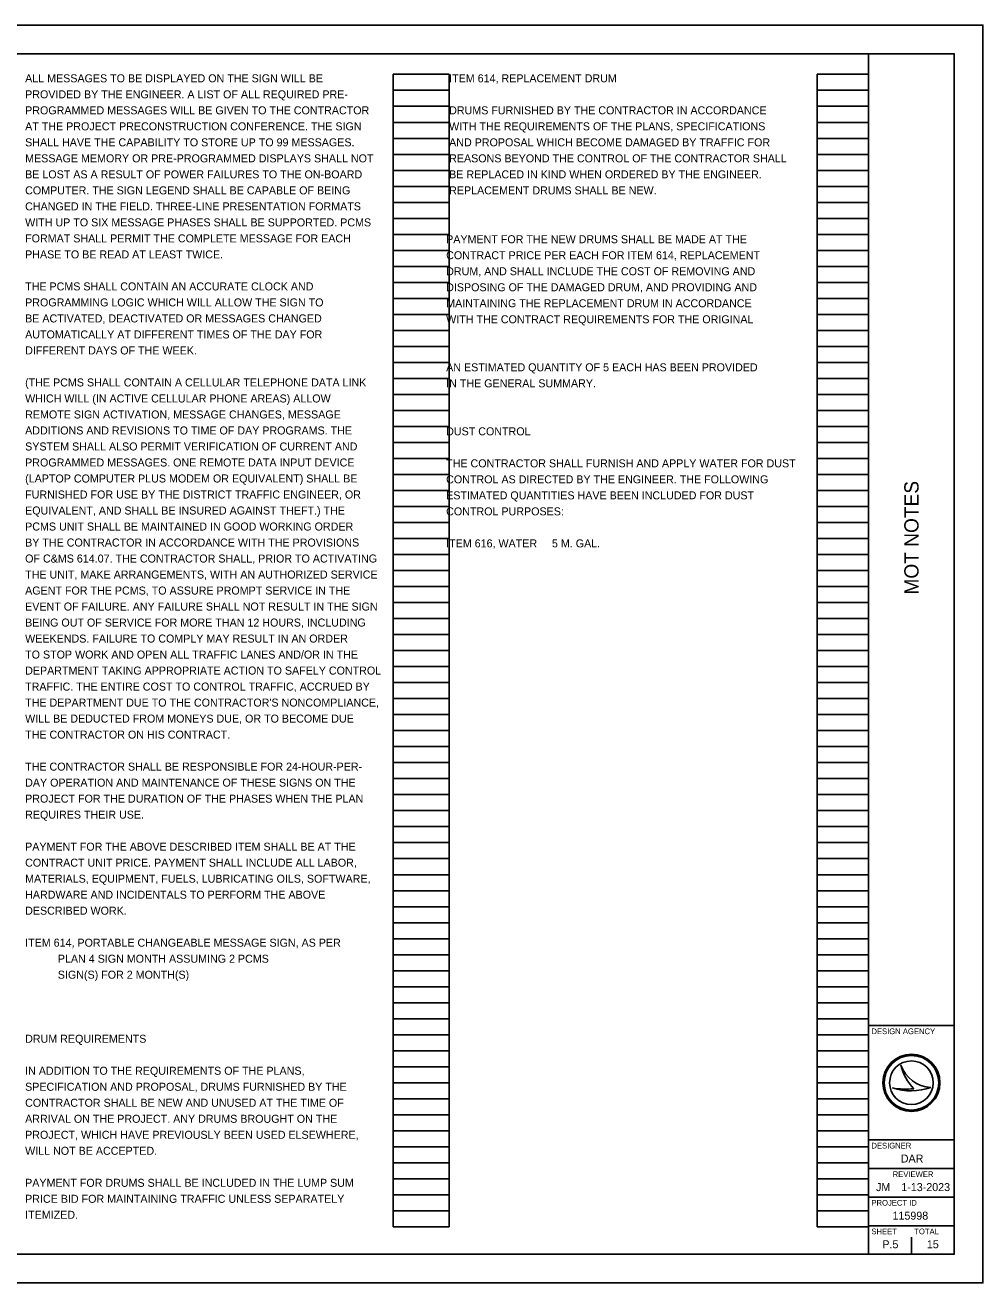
# Model space of a CAD drawing. Extents: x 0 to 34, y 0 to 22.
# Drawn here: x 17.24 to 34, y 0 to 22 of the extents above; entities that cross this region are included whole.
import ezdxf

# ---------------------------------------------------------------- set-up
doc = ezdxf.new("R2010")
doc.units = 0
for name, color, linetype in [('SH_Border', 7, 'Continuous'), ('SH_Cut_Line', 7, 'Continuous'), ('SH_Data', 7, 'Continuous'), ('SH_Text', 7, 'Continuous')]:
    doc.layers.add(name, color=color, linetype=linetype)

msp = doc.modelspace()

# ---------------------------------------------------------------- linework, layer by layer
at = {"layer": 'SH_Border'}
for p, q in [((32, 0.5), (32, 21.5)), ((32, 4.5), (33.5, 4.5)), ((32, 2.5), (33.5, 2.5)), ((32, 2), (33.5, 2)), ((32, 1.5), (33.5, 1.5)), ((32, 1), (33.5, 1))]:
    msp.add_line(p, q, dxfattribs=at)
msp.add_lwpolyline([(1.5, 21.5), (33.5, 21.5), (33.5, 0.5), (1.5, 0.5)], close=True, dxfattribs=at)
at = {"layer": 'SH_Cut_Line'}
msp.add_lwpolyline([(0, 0), (34, 0), (34, 22), (0, 22)], close=True, dxfattribs=at)
at = {"layer": 'SH_Data'}
for p, q in [((23.68, 0.98), (23.68, 21.14)), ((23.68, 21.14), (24.66, 21.14)), ((24.66, 0.98), (24.66, 21.14)), ((31.1, 0.98), (31.1, 21.14)), ((31.1, 21.14), (32, 21.14)), ((32, 0.98), (32, 21.14)), ((23.68, 20.86), (24.66, 20.86)), ((31.1, 20.86), (32, 20.86)), ((23.68, 20.58), (24.66, 20.58)), ((31.1, 20.58), (32, 20.58)), ((23.68, 20.3), (24.66, 20.3)), ((31.1, 20.3), (32, 20.3)), ((23.68, 20.02), (24.66, 20.02)), ((31.1, 20.02), (32, 20.02)), ((23.68, 19.74), (24.66, 19.74)), ((31.1, 19.74), (32, 19.74)), ((23.68, 19.46), (24.66, 19.46)), ((31.1, 19.46), (32, 19.46)), ((23.68, 19.18), (24.66, 19.18)), ((31.1, 19.18), (32, 19.18)), ((23.68, 18.9), (24.66, 18.9)), ((31.1, 18.9), (32, 18.9)), ((23.68, 18.62), (24.66, 18.62)), ((31.1, 18.62), (32, 18.62)), ((23.68, 18.34), (24.66, 18.34)), ((31.1, 18.34), (32, 18.34)), ((23.68, 18.06), (24.66, 18.06)), ((31.1, 18.06), (32, 18.06)), ((23.68, 17.78), (24.66, 17.78)), ((31.1, 17.78), (32, 17.78)), ((23.68, 17.5), (24.66, 17.5)), ((31.1, 17.5), (32, 17.5)), ((23.68, 17.22), (24.66, 17.22)), ((31.1, 17.22), (32, 17.22)), ((23.68, 16.94), (24.66, 16.94)), ((31.1, 16.94), (32, 16.94)), ((23.68, 16.66), (24.66, 16.66)), ((31.1, 16.66), (32, 16.66)), ((23.68, 16.38), (24.66, 16.38)), ((31.1, 16.38), (32, 16.38)), ((23.68, 16.1), (24.66, 16.1)), ((31.1, 16.1), (32, 16.1)), ((23.68, 15.82), (24.66, 15.82)), ((31.1, 15.82), (32, 15.82)), ((23.68, 15.54), (24.66, 15.54)), ((31.1, 15.54), (32, 15.54)), ((23.68, 15.26), (24.66, 15.26)), ((31.1, 15.26), (32, 15.26)), ((23.68, 14.98), (24.66, 14.98)), ((31.1, 14.98), (32, 14.98)), ((23.68, 14.7), (24.66, 14.7)), ((31.1, 14.7), (32, 14.7)), ((23.68, 14.42), (24.66, 14.42)), ((31.1, 14.42), (32, 14.42)), ((23.68, 14.14), (24.66, 14.14)), ((31.1, 14.14), (32, 14.14)), ((23.68, 13.86), (24.66, 13.86)), ((31.1, 13.86), (32, 13.86)), ((23.68, 13.58), (24.66, 13.58)), ((31.1, 13.58), (32, 13.58)), ((23.68, 13.3), (24.66, 13.3)), ((31.1, 13.3), (32, 13.3)), ((23.68, 13.02), (24.66, 13.02)), ((31.1, 13.02), (32, 13.02)), ((23.68, 12.74), (24.66, 12.74)), ((31.1, 12.74), (32, 12.74)), ((23.68, 12.46), (24.66, 12.46)), ((31.1, 12.46), (32, 12.46)), ((23.68, 12.18), (24.66, 12.18)), ((31.1, 12.18), (32, 12.18)), ((23.68, 11.9), (24.66, 11.9)), ((31.1, 11.9), (32, 11.9)), ((23.68, 11.62), (24.66, 11.62)), ((31.1, 11.62), (32, 11.62)), ((23.68, 11.34), (24.66, 11.34)), ((31.1, 11.34), (32, 11.34)), ((23.68, 11.06), (24.66, 11.06)), ((31.1, 11.06), (32, 11.06)), ((23.68, 10.78), (24.66, 10.78)), ((31.1, 10.78), (32, 10.78)), ((23.68, 10.5), (24.66, 10.5)), ((31.1, 10.5), (32, 10.5)), ((23.68, 10.22), (24.66, 10.22)), ((31.1, 10.22), (32, 10.22)), ((23.68, 9.94), (24.66, 9.94)), ((31.1, 9.94), (32, 9.94)), ((23.68, 9.66), (24.66, 9.66)), ((31.1, 9.66), (32, 9.66)), ((23.68, 9.38), (24.66, 9.38)), ((31.1, 9.38), (32, 9.38)), ((23.68, 9.1), (24.66, 9.1)), ((31.1, 9.1), (32, 9.1)), ((23.68, 8.82), (24.66, 8.82)), ((31.1, 8.82), (32, 8.82)), ((23.68, 8.54), (24.66, 8.54)), ((31.1, 8.54), (32, 8.54)), ((23.68, 8.26), (24.66, 8.26)), ((31.1, 8.26), (32, 8.26)), ((23.68, 7.98), (24.66, 7.98)), ((31.1, 7.98), (32, 7.98)), ((23.68, 7.7), (24.66, 7.7)), ((31.1, 7.7), (32, 7.7)), ((23.68, 7.42), (24.66, 7.42)), ((31.1, 7.42), (32, 7.42)), ((23.68, 7.14), (24.66, 7.14)), ((31.1, 7.14), (32, 7.14)), ((23.68, 6.86), (24.66, 6.86)), ((31.1, 6.86), (32, 6.86)), ((23.68, 6.58), (24.66, 6.58)), ((31.1, 6.58), (32, 6.58)), ((23.68, 6.3), (24.66, 6.3)), ((31.1, 6.3), (32, 6.3)), ((23.68, 6.02), (24.66, 6.02)), ((31.1, 6.02), (32, 6.02)), ((23.68, 5.74), (24.66, 5.74)), ((31.1, 5.74), (32, 5.74)), ((23.68, 5.46), (24.66, 5.46)), ((31.1, 5.46), (32, 5.46)), ((23.68, 5.18), (24.66, 5.18)), ((31.1, 5.18), (32, 5.18)), ((23.68, 4.9), (24.66, 4.9)), ((31.1, 4.9), (32, 4.9)), ((23.68, 4.62), (24.66, 4.62)), ((31.1, 4.62), (32, 4.62)), ((23.68, 4.34), (24.66, 4.34)), ((31.1, 4.34), (32, 4.34)), ((23.68, 4.06), (24.66, 4.06)), ((31.1, 4.06), (32, 4.06)), ((23.68, 3.78), (24.66, 3.78)), ((31.1, 3.78), (32, 3.78)), ((32.567, 3.81), (32.567, 3.81)), ((23.68, 3.5), (24.66, 3.5)), ((31.1, 3.5), (32, 3.5)), ((32.417, 3.41), (32.417, 3.41)), ((32.75, 3.5), (32.75, 3.5)), ((33.087, 3.419), (33.087, 3.419)), ((23.68, 3.22), (24.66, 3.22)), ((31.1, 3.22), (32, 3.22)), ((23.68, 2.94), (24.66, 2.94)), ((31.1, 2.94), (32, 2.94)), ((23.68, 2.66), (24.66, 2.66)), ((31.1, 2.66), (32, 2.66)), ((23.68, 2.38), (24.66, 2.38)), ((31.1, 2.38), (32, 2.38)), ((23.68, 2.1), (24.66, 2.1)), ((31.1, 2.1), (32, 2.1)), ((23.68, 1.82), (24.66, 1.82)), ((31.1, 1.82), (32, 1.82)), ((23.68, 1.54), (24.66, 1.54)), ((31.1, 1.54), (32, 1.54)), ((23.68, 1.26), (24.66, 1.26)), ((31.1, 1.26), (32, 1.26)), ((23.68, 0.98), (24.66, 0.98)), ((31.1, 0.98), (32, 0.98)), ((32.375, 0.675), (32.375, 0.675)), ((32.75, 0.5), (32.75, 0.8))]:
    msp.add_line(p, q, dxfattribs=at)
for radius in [0.5, 0.477, 0.477, 0.382]:
    msp.add_circle((32.75, 3.5), radius, dxfattribs=at)
for centre, radius, start, end in [((33.116, 3.998), 0.58, 198.9257, 198.9319), ((33.347, 3.97), 0.796, 191.6379, 191.6421), ((33.116, 3.998), 0.58, 198.9319, 267.1657), ((33.347, 3.97), 0.796, 191.6421, 226.0947), ((32.739, 4.37), 1.013, 251.4576, 290.0832), ((32.648, 4.654), 1.266, 259.4964, 259.4995), ((32.739, 4.37), 1.013, 251.4527, 251.4576), ((32.648, 4.654), 1.266, 259.4995, 276.6672)]:
    msp.add_arc(centre, radius, start, end, dxfattribs=at)

# ---------------------------------------------------------------- texts
msp.add_text('MOT NOTES', height=0.25, rotation=90, dxfattribs=at).set_placement((32.875, 12.04))
for s, height, p in [('DESIGN AGENCY', 0.1, (32.05, 4.35)), ('DESIGNER', 0.1, (32.05, 2.35)), ('DAR', 0.14, (32.564, 2.105)), ('REVIEWER', 0.1, (32.422, 1.85)), ('JM', 0.14, (32.13, 1.605)), ('1-13-2023', 0.14, (32.573, 1.605)), ('PROJECT ID', 0.1, (32.05, 1.35)), ('115998', 0.14, (32.419, 1.105)), ('SHEET', 0.1, (32.05, 0.85)), ('TOTAL', 0.1, (32.8, 0.85)), ('P.5', 0.14, (32.241, 0.605)), ('15', 0.14, (33.02, 0.605))]:
    msp.add_text(s, height=height, dxfattribs=at).set_placement(p)
at = {"layer": 'SH_Text'}
for s, p in [('ALL MESSAGES TO BE DISPLAYED ON THE SIGN WILL BE', (17.24, 21)), ('ITEM 614, REPLACEMENT DRUM', (24.66, 21)), ('PROVIDED BY THE ENGINEER. A LIST OF ALL REQUIRED PRE-', (17.24, 20.72)), ('PROGRAMMED MESSAGES WILL BE GIVEN TO THE CONTRACTOR', (17.24, 20.44)), ('DRUMS FURNISHED BY THE CONTRACTOR IN ACCORDANCE', (24.66, 20.44)), ('AT THE PROJECT PRECONSTRUCTION CONFERENCE. THE SIGN', (17.24, 20.16)), ('WITH THE REQUIREMENTS OF THE PLANS, SPECIFICATIONS', (24.66, 20.16)), ('SHALL HAVE THE CAPABILITY TO STORE UP TO 99 MESSAGES.', (17.24, 19.88)), ('AND PROPOSAL WHICH BECOME DAMAGED BY TRAFFIC FOR', (24.66, 19.88)), ('MESSAGE MEMORY OR PRE-PROGRAMMED DISPLAYS SHALL NOT', (17.24, 19.6)), ('REASONS BEYOND THE CONTROL OF THE CONTRACTOR SHALL', (24.66, 19.6)), ('BE LOST AS A RESULT OF POWER FAILURES TO THE ON-BOARD', (17.24, 19.32)), ('BE REPLACED IN KIND WHEN ORDERED BY THE ENGINEER.', (24.66, 19.32)), ('COMPUTER. THE SIGN LEGEND SHALL BE CAPABLE OF BEING', (17.24, 19.04)), ('REPLACEMENT DRUMS SHALL BE NEW.', (24.66, 19.04)), ('CHANGED IN THE FIELD. THREE-LINE PRESENTATION FORMATS', (17.24, 18.76)), ('WITH UP TO SIX MESSAGE PHASES SHALL BE SUPPORTED. PCMS', (17.24, 18.48)), ('FORMAT SHALL PERMIT THE COMPLETE MESSAGE FOR EACH', (17.24, 18.2)), ('PAYMENT FOR THE NEW DRUMS SHALL BE MADE AT THE', (24.608, 18.185)), ('PHASE TO BE READ AT LEAST TWICE.', (17.24, 17.92)), ('CONTRACT PRICE PER EACH FOR ITEM 614, REPLACEMENT', (24.608, 17.905)), ('DRUM, AND SHALL INCLUDE THE COST OF REMOVING AND', (24.608, 17.625)), ('THE PCMS SHALL CONTAIN AN ACCURATE CLOCK AND', (17.24, 17.36)), ('DISPOSING OF THE DAMAGED DRUM, AND PROVIDING AND', (24.608, 17.345)), ('PROGRAMMING LOGIC WHICH WILL ALLOW THE SIGN TO', (17.24, 17.08)), ('MAINTAINING THE REPLACEMENT DRUM IN ACCORDANCE', (24.608, 17.065)), ('BE ACTIVATED, DEACTIVATED OR MESSAGES CHANGED', (17.24, 16.8)), ('WITH THE CONTRACT REQUIREMENTS FOR THE ORIGINAL', (24.608, 16.785)), ('AUTOMATICALLY AT DIFFERENT TIMES OF THE DAY FOR', (17.24, 16.52)), ('DIFFERENT DAYS OF THE WEEK.', (17.24, 16.24)), ('AN ESTIMATED QUANTITY OF 5 EACH HAS BEEN PROVIDED', (24.608, 15.945)), ('(THE PCMS SHALL CONTAIN A CELLULAR TELEPHONE DATA LINK', (17.24, 15.68)), ('IN THE GENERAL SUMMARY.', (24.608, 15.665)), ('WHICH WILL (IN ACTIVE CELLULAR PHONE AREAS) ALLOW', (17.24, 15.4)), ('REMOTE SIGN ACTIVATION, MESSAGE CHANGES, MESSAGE', (17.24, 15.12)), ('ADDITIONS AND REVISIONS TO TIME OF DAY PROGRAMS. THE', (17.24, 14.84)), ('DUST CONTROL', (24.608, 14.825)), ('SYSTEM SHALL ALSO PERMIT VERIFICATION OF CURRENT AND', (17.24, 14.56)), ('PROGRAMMED MESSAGES. ONE REMOTE DATA INPUT DEVICE', (17.24, 14.28)), ('THE CONTRACTOR SHALL FURNISH AND APPLY WATER FOR DUST', (24.608, 14.265)), ('(LAPTOP COMPUTER PLUS MODEM OR EQUIVALENT) SHALL BE', (17.24, 14)), ('CONTROL AS DIRECTED BY THE ENGINEER. THE FOLLOWING', (24.608, 13.985)), ('FURNISHED FOR USE BY THE DISTRICT TRAFFIC ENGINEER, OR', (17.24, 13.72)), ('ESTIMATED QUANTITIES HAVE BEEN INCLUDED FOR DUST', (24.608, 13.705)), ('EQUIVALENT, AND SHALL BE INSURED AGAINST THEFT.) THE', (17.24, 13.44)), ('CONTROL PURPOSES:', (24.608, 13.425)), ('PCMS UNIT SHALL BE MAINTAINED IN GOOD WORKING ORDER', (17.24, 13.16)), ('BY THE CONTRACTOR IN ACCORDANCE WITH THE PROVISIONS', (17.24, 12.88)), ('ITEM 616, WATER     5 M. GAL.', (24.608, 12.865)), ('OF C&MS 614.07. THE CONTRACTOR SHALL, PRIOR TO ACTIVATING', (17.24, 12.6)), ('THE UNIT, MAKE ARRANGEMENTS, WITH AN AUTHORIZED SERVICE', (17.24, 12.32)), ('AGENT FOR THE PCMS, TO ASSURE PROMPT SERVICE IN THE', (17.24, 12.04)), ('EVENT OF FAILURE. ANY FAILURE SHALL NOT RESULT IN THE SIGN', (17.24, 11.76)), ('BEING OUT OF SERVICE FOR MORE THAN 12 HOURS, INCLUDING', (17.24, 11.48)), ('WEEKENDS. FAILURE TO COMPLY MAY RESULT IN AN ORDER', (17.24, 11.2)), ('TO STOP WORK AND OPEN ALL TRAFFIC LANES AND/OR IN THE', (17.24, 10.92)), ('DEPARTMENT TAKING APPROPRIATE ACTION TO SAFELY CONTROL', (17.24, 10.64)), ('TRAFFIC. THE ENTIRE COST TO CONTROL TRAFFIC, ACCRUED BY', (17.24, 10.36)), ("THE DEPARTMENT DUE TO THE CONTRACTOR'S NONCOMPLIANCE,", (17.24, 10.08)), ('WILL BE DEDUCTED FROM MONEYS DUE, OR TO BECOME DUE', (17.24, 9.8)), ('THE CONTRACTOR ON HIS CONTRACT.', (17.24, 9.52)), ('THE CONTRACTOR SHALL BE RESPONSIBLE FOR 24-HOUR-PER-', (17.24, 8.96)), ('DAY OPERATION AND MAINTENANCE OF THESE SIGNS ON THE', (17.24, 8.68)), ('PROJECT FOR THE DURATION OF THE PHASES WHEN THE PLAN', (17.24, 8.4)), ('REQUIRES THEIR USE.', (17.24, 8.12)), ('PAYMENT FOR THE ABOVE DESCRIBED ITEM SHALL BE AT THE', (17.24, 7.56)), ('CONTRACT UNIT PRICE. PAYMENT SHALL INCLUDE ALL LABOR,', (17.24, 7.28)), ('MATERIALS, EQUIPMENT, FUELS, LUBRICATING OILS, SOFTWARE,', (17.24, 7)), ('HARDWARE AND INCIDENTALS TO PERFORM THE ABOVE', (17.24, 6.72)), ('DESCRIBED WORK.', (17.24, 6.44)), ('ITEM 614, PORTABLE CHANGEABLE MESSAGE SIGN, AS PER', (17.24, 5.88)), ('           PLAN 4 SIGN MONTH ASSUMING 2 PCMS', (17.24, 5.6)), ('           SIGN(S) FOR 2 MONTH(S)', (17.24, 5.32)), ('DRUM REQUIREMENTS', (17.24, 4.2)), ('IN ADDITION TO THE REQUIREMENTS OF THE PLANS,', (17.24, 3.64)), ('SPECIFICATION AND PROPOSAL, DRUMS FURNISHED BY THE', (17.24, 3.36)), ('CONTRACTOR SHALL BE NEW AND UNUSED AT THE TIME OF', (17.24, 3.08)), ('ARRIVAL ON THE PROJECT. ANY DRUMS BROUGHT ON THE', (17.24, 2.8)), ('PROJECT, WHICH HAVE PREVIOUSLY BEEN USED ELSEWHERE,', (17.24, 2.52)), ('WILL NOT BE ACCEPTED.', (17.24, 2.24)), ('PAYMENT FOR DRUMS SHALL BE INCLUDED IN THE LUMP SUM', (17.24, 1.68)), ('PRICE BID FOR MAINTAINING TRAFFIC UNLESS SEPARATELY', (17.24, 1.4)), ('ITEMIZED.', (17.24, 1.12))]:
    msp.add_text(s, height=0.14, dxfattribs=at).set_placement(p)

doc.saveas('drawing.dxf')
